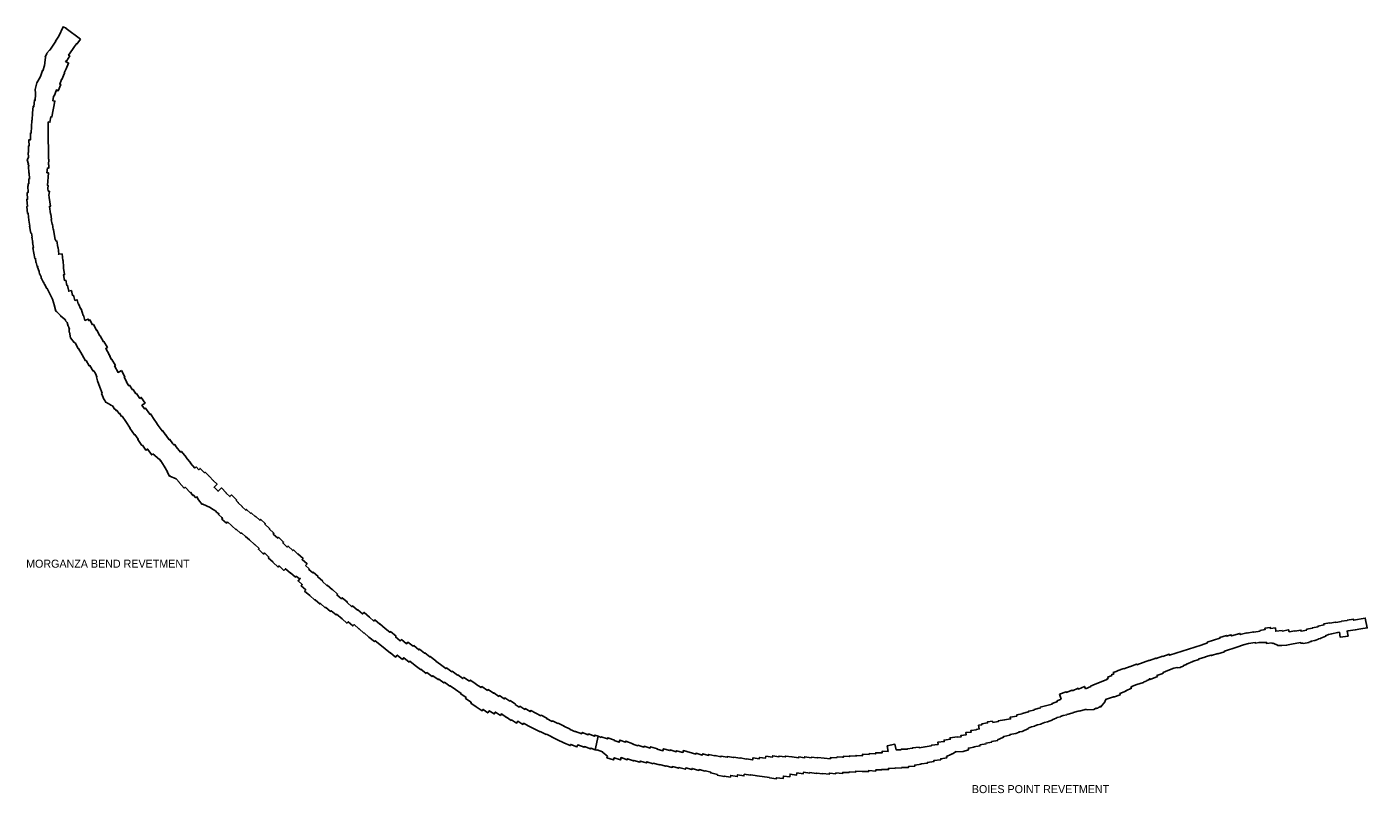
# Model space of a CAD drawing. Extents: x 2650582 to 3923188, y 277893 to 989177.
# Drawn here: x 3197064 to 3223870, y 809785 to 825119 of the extents above; entities that cross this region are included whole.
import ezdxf

# ---------------------------------------------------------------- set-up
doc = ezdxf.new("R2010")
doc.units = 0
doc.layers.add('Level 3', color=7, linetype='Continuous')

msp = doc.modelspace()

# ---------------------------------------------------------------- linework, layer by layer
at = {"layer": 'Level 3'}
for points in [[(3198137, 824875), (3197849, 825082), (3197852, 825090), (3197790, 825119), (3197703, 824935), (3197708, 824932), (3197640, 824831), (3197644, 824829), (3197593, 824751), (3197589, 824754), (3197522, 824651), (3197521, 824652), (3197463, 824590), (3197467, 824586), (3197462, 824588), (3197434, 824513), (3197436, 824513), (3197423, 824395), (3197424, 824395), (3197422, 824389), (3197423, 824389), (3197421, 824348), (3197382, 824240), (3197375, 824242), (3197341, 824128), (3197337, 824129), (3197334, 824111), (3197267, 823995), (3197262, 823996), (3197232, 823865), (3197234, 823865), (3197235, 823790), (3197240, 823767)], [(3197585, 823641), (3197598, 823722), (3197599, 823722), (3197602, 823737), (3197610, 823734), (3197656, 823855), (3197694, 823840), (3197743, 823965), (3197722, 823974), (3197760, 824068), (3197767, 824065), (3197820, 824194), (3197814, 824196), (3197850, 824279), (3197852, 824279), (3197901, 824393), (3197841, 824425), (3197848, 824437), (3197855, 824433), (3197922, 824535), (3197901, 824549), (3197976, 824664), (3198019, 824725), (3198017, 824727), (3198055, 824781), (3198064, 824775), (3198137, 824875)], [(3197240, 823767), (3197232, 823651), (3197215, 823652), (3197205, 823524), (3197189, 823525), (3197180, 823395), (3197176, 823395), (3197169, 823254), (3197165, 823254), (3197159, 823117), (3197160, 823116), (3197154, 822995), (3197140, 822995), (3197139, 822860), (3197108, 822860), (3197110, 822732), (3197097, 822732), (3197098, 822602), (3197093, 822602), (3197095, 822505), (3197074, 822459), (3197079, 822457), (3197072, 822455), (3197095, 822374), (3197090, 822372), (3197102, 822335), (3197102, 822330), (3197101, 822330), (3197104, 822197), (3197111, 822197), (3197115, 822073), (3197102, 822072), (3197105, 821981), (3197093, 821981), (3197093, 821936), (3197084, 821935), (3197091, 821803), (3197072, 821802), (3197079, 821666), (3197064, 821665), (3197078, 821527), (3197067, 821526), (3197081, 821385), (3197093, 821386), (3197108, 821252), (3197126, 821130), (3197118, 821128), (3197145, 820990), (3197155, 820992), (3197173, 820910)], [(3197494, 822468), (3197495, 822468), (3197493, 823064), (3197493, 823216), (3197526, 823210), (3197547, 823320), (3197566, 823316), (3197628, 823633), (3197585, 823641)], [(3197693, 820569), (3197693, 820570), (3197705, 820571), (3197689, 820706), (3197682, 820705), (3197668, 820834), (3197646, 820832), (3197641, 820858), (3197632, 820857), (3197599, 821065), (3197594, 821064), (3197577, 821168), (3197571, 821167), (3197554, 821265), (3197561, 821266), (3197543, 821376), (3197536, 821375), (3197515, 821524), (3197538, 821528), (3197511, 821707), (3197513, 821716), (3197510, 821717), (3197506, 821741), (3197516, 821828), (3197493, 821831), (3197485, 821886), (3197491, 821944), (3197476, 821946), (3197476, 821946), (3197501, 822195), (3197468, 822198), (3197480, 822295), (3197505, 822294), (3197506, 822353), (3197501, 822355), (3197505, 822468), (3197494, 822468)], [(3197173, 820910), (3197167, 820908), (3197183, 820804), (3197177, 820803), (3197195, 820701), (3197186, 820700), (3197222, 820486), (3197237, 820487), (3197247, 820404), (3197249, 820404), (3197270, 820325), (3197281, 820328), (3197284, 820313), (3197277, 820310), (3197309, 820222), (3197311, 820223), (3197320, 820171), (3197325, 820172), (3197349, 820115), (3197354, 820085), (3197361, 820086), (3197398, 820001), (3197407, 820005), (3197413, 819971), (3197421, 819972), (3197468, 819880), (3197470, 819881), (3197576, 819670), (3197580, 819673), (3197620, 819533), (3197615, 819532), (3197645, 819429), (3197655, 819432), (3197660, 819417), (3197666, 819419), (3197741, 819340), (3197744, 819331), (3197746, 819331), (3197835, 819253), (3197841, 819235), (3197870, 819201), (3197892, 819129), (3197896, 819131), (3197906, 819104), (3197919, 819071), (3197914, 819071), (3197914, 819009), (3197919, 819009), (3197937, 818898), (3197940, 818898), (3198013, 818804), (3198015, 818805), (3198017, 818800), (3198023, 818802), (3198035, 818792)], [(3198381, 819157), (3198327, 819254), (3198302, 819240), (3198290, 819271), (3198226, 819246), (3198196, 819347), (3198194, 819346), (3198152, 819473), (3198145, 819470), (3198097, 819579), (3198094, 819578), (3198069, 819658), (3198025, 819644), (3197996, 819748), (3197978, 819744), (3197955, 819841), (3197904, 819829), (3197880, 819945), (3197868, 819943), (3197847, 820049), (3197818, 820044), (3197798, 820156), (3197821, 820160), (3197801, 820287), (3197801, 820287), (3197798, 820309), (3197801, 820309), (3197791, 820445), (3197783, 820444), (3197770, 820576), (3197693, 820569)], [(3198959, 818242), (3198891, 818205), (3198819, 818333), (3198838, 818345), (3198766, 818465), (3198760, 818461), (3198724, 818522), (3198732, 818528), (3198708, 818562), (3198712, 818564), (3198644, 818684), (3198678, 818705), (3198606, 818822), (3198600, 818819), (3198531, 818938), (3198526, 818935), (3198466, 819051), (3198457, 819047), (3198398, 819166), (3198381, 819157)], [(3198035, 818792), (3198094, 818679), (3198099, 818682), (3198172, 818556), (3198169, 818554), (3198240, 818439), (3198250, 818445), (3198313, 818333), (3198327, 818340), (3198392, 818231), (3198404, 818238), (3198437, 818184), (3198453, 818146), (3198454, 818147), (3198466, 818118), (3198459, 818117), (3198479, 818039), (3198476, 818038), (3198527, 817908), (3198522, 817906), (3198571, 817787), (3198559, 817782), (3198614, 817653), (3198620, 817655), (3198643, 817604), (3198648, 817606), (3198738, 817557), (3198739, 817556), (3198740, 817556), (3198742, 817555), (3198745, 817550), (3198748, 817552), (3198775, 817537)], [(3200053, 816715), (3200022, 816765), (3200003, 816753), (3199983, 816778), (3199926, 816863), (3199914, 816855), (3199853, 816943), (3199852, 816942), (3199840, 816960), (3199837, 816958), (3199780, 817039), (3199770, 817032), (3199694, 817140), (3199693, 817139), (3199642, 817213), (3199625, 817242), (3199628, 817244), (3199535, 817376), (3199522, 817367), (3199437, 817492), (3199415, 817476), (3199367, 817547), (3199431, 817591), (3199354, 817704), (3199325, 817684), (3199257, 817783), (3199248, 817776), (3199189, 817865), (3199177, 817857), (3199119, 817949), (3199102, 817938), (3199059, 818008), (3199068, 818012), (3199012, 818111), (3199025, 818119), (3198959, 818242)], [(3198775, 817537), (3198825, 817463), (3198833, 817468), (3198856, 817436), (3198868, 817444), (3198911, 817381), (3198918, 817386), (3198960, 817325), (3198969, 817331), (3199043, 817224), (3199042, 817223), (3199131, 817092), (3199125, 817088), (3199217, 816956), (3199225, 816961), (3199292, 816866), (3199284, 816860), (3199367, 816743), (3199375, 816748), (3199446, 816648), (3199479, 816671), (3199562, 816554), (3199588, 816572)], [(3199588, 816572), (3199715, 816463), (3199720, 816468), (3199743, 816431), (3199747, 816434), (3199814, 816328), (3199813, 816327), (3199880, 816217), (3199873, 816213), (3199918, 816131), (3199929, 816138), (3199926, 816130), (3200051, 816074), (3200115, 816001), (3200112, 815999), (3200214, 815889), (3200232, 815906), (3200335, 815795), (3200347, 815805), (3200355, 815796), (3200348, 815791), (3200385, 815740), (3200398, 815749), (3200446, 815698), (3200466, 815716), (3200496, 815656), (3200572, 815562), (3200585, 815572), (3200583, 815568), (3200730, 815503), (3200730, 815503), (3200779, 815465), (3200779, 815466), (3200839, 815433), (3200863, 815403), (3200908, 815374), (3200897, 815362), (3200964, 815301), (3200979, 815284), (3200964, 815268), (3201056, 815185), (3201080, 815212)], [(3201248, 815643), (3201259, 815654), (3201160, 815753), (3201126, 815719), (3201049, 815790), (3201054, 815794), (3200955, 815893), (3200889, 815828), (3200811, 815906), (3200871, 815965), (3200794, 816042), (3200794, 816042), (3200717, 816119), (3200717, 816120), (3200629, 816207), (3200619, 816197), (3200530, 816285), (3200504, 816258), (3200452, 816314), (3200427, 816290), (3200341, 816388), (3200345, 816391), (3200249, 816502), (3200253, 816506), (3200155, 816624), (3200139, 816611), (3200054, 816715), (3200053, 816715)], [(3202637, 814338), (3202670, 814375), (3202571, 814460), (3202591, 814482), (3202485, 814574), (3202482, 814571), (3202395, 814652), (3202384, 814641), (3202289, 814730), (3202272, 814711), (3202184, 814793), (3202201, 814811), (3202098, 814907), (3202082, 814889), (3201994, 814971), (3202007, 814985), (3201912, 815074), (3201920, 815082), (3201825, 815170), (3201833, 815179), (3201742, 815264), (3201725, 815245), (3201642, 815323), (3201635, 815316), (3201552, 815394), (3201543, 815384), (3201460, 815462), (3201446, 815447), (3201370, 815518), (3201372, 815521), (3201289, 815598), (3201292, 815602), (3201248, 815643)], [(3201080, 815212), (3201166, 815132), (3201167, 815134), (3201251, 815056), (3201258, 815064), (3201341, 814986), (3201346, 814992), (3201357, 814982), (3201364, 814989), (3201437, 814922), (3201439, 814924), (3201515, 814853), (3201515, 814853), (3201618, 814758), (3201623, 814763), (3201711, 814682), (3201697, 814667), (3201799, 814571), (3201819, 814592), (3201906, 814510), (3201893, 814496), (3201988, 814407), (3201987, 814406), (3202089, 814310), (3202110, 814333), (3202205, 814244), (3202235, 814276), (3202335, 814189), (3202338, 814191), (3202436, 814106), (3202454, 814127)], [(3202454, 814127), (3202521, 814071), (3202531, 814083), (3202533, 814082), (3202490, 814031), (3202574, 813958), (3202554, 813934), (3202643, 813856), (3202621, 813830), (3202726, 813740), (3202724, 813738), (3202822, 813649), (3202828, 813655), (3202928, 813569), (3202939, 813582), (3203033, 813497), (3203041, 813506), (3203139, 813421), (3203152, 813435), (3203248, 813352), (3203259, 813365), (3203368, 813271), (3203370, 813273), (3203467, 813186), (3203493, 813215), (3203587, 813132), (3203611, 813160), (3203706, 813075), (3203708, 813077), (3203806, 812990), (3203808, 812992), (3203904, 812908), (3203906, 812910), (3204016, 812819), (3204031, 812836), (3204124, 812760), (3204127, 812763), (3204232, 812674), (3204233, 812674), (3204335, 812587), (3204339, 812591), (3204439, 812508), (3204472, 812548), (3204575, 812462), (3204604, 812496), (3204710, 812407), (3204724, 812424), (3204828, 812337), (3204832, 812342), (3204936, 812258), (3204941, 812264), (3205050, 812180)], [(3205241, 812428), (3205246, 812435), (3205133, 812522), (3205125, 812513), (3205026, 812593), (3205019, 812585), (3204919, 812668), (3204906, 812653), (3204803, 812740), (3204789, 812724), (3204687, 812810), (3204658, 812775), (3204557, 812859), (3204534, 812831), (3204438, 812912), (3204449, 812925), (3204338, 813020), (3204325, 813005), (3204232, 813081), (3204124, 813171), (3204121, 813168), (3204023, 813253), (3204003, 813230), (3203915, 813307), (3203809, 813403), (3203781, 813371), (3203686, 813455), (3203680, 813449), (3203581, 813536), (3203564, 813517), (3203471, 813599), (3203477, 813605), (3203372, 813697), (3203355, 813677), (3203266, 813754), (3203279, 813768), (3203179, 813858), (3203176, 813855), (3203072, 813946), (3203067, 813940), (3202978, 814020), (3202983, 814025), (3202883, 814111), (3202890, 814119), (3202791, 814206), (3202782, 814195), (3202702, 814264), (3202710, 814273), (3202637, 814338)], [(3222660, 813046), (3222657, 813065), (3222773, 813086), (3222771, 813093), (3222888, 813116), (3222886, 813130), (3223004, 813152), (3223001, 813171), (3223120, 813192), (3223122, 813188), (3223239, 813209), (3223241, 813203), (3223354, 813222), (3223353, 813226), (3223472, 813241), (3223472, 813244), (3223596, 813265), (3223599, 813245), (3223832, 813288), (3223870, 813093), (3223745, 813074), (3223745, 813076), (3223632, 813057), (3223632, 813051), (3223490, 813032), (3223469, 813029), (3223486, 812929), (3223331, 812904), (3223315, 813007), (3223276, 813001), (3223276, 812998), (3223161, 812977), (3223161, 812974), (3223094, 812962), (3223039, 812937), (3223042, 812927), (3222945, 812886), (3222940, 812893), (3222940, 812879), (3222894, 812873), (3222894, 812867), (3222823, 812840), (3222823, 812838), (3222749, 812827), (3222750, 812820), (3222706, 812806), (3222707, 812803), (3222588, 812778)], [(3219779, 812528), (3219783, 812518), (3219910, 812565), (3219917, 812546), (3220299, 812669), (3220299, 812668), (3220421, 812708), (3220422, 812704), (3220548, 812750), (3220674, 812791), (3220670, 812804), (3220924, 812886), (3220921, 812900), (3221053, 812943), (3221060, 812927), (3221146, 812955), (3221155, 812931), (3221323, 812982), (3221331, 812960), (3221465, 812995), (3221466, 812989), (3221600, 813012), (3221601, 813007), (3221728, 813029), (3221726, 813040), (3221829, 813059), (3221826, 813090)], [(3221826, 813090), (3221932, 813101), (3221934, 813081), (3222033, 813091), (3222040, 813027), (3222169, 813038), (3222170, 813024)], [(3222170, 813024), (3222299, 813054), (3222309, 813013)], [(3222309, 813013), (3222423, 813034), (3222425, 813030), (3222543, 813050), (3222549, 813026), (3222660, 813046)], [(3221968, 812791), (3221859, 812780), (3221857, 812801), (3221799, 812799), (3221798, 812803), (3221768, 812797), (3221767, 812800), (3221709, 812801), (3221709, 812803), (3221633, 812789), (3221630, 812800), (3221497, 812778), (3221396, 812754), (3221263, 812707), (3221263, 812709), (3221013, 812627), (3221016, 812616), (3220884, 812572), (3220881, 812580), (3220754, 812538), (3220751, 812550), (3220630, 812511), (3220631, 812508), (3220501, 812471), (3220504, 812461), (3220378, 812423), (3220380, 812417), (3220255, 812370), (3220258, 812360), (3220193, 812337), (3220196, 812330), (3220134, 812307), (3220134, 812302), (3220068, 812295), (3220068, 812303), (3220005, 812285), (3219884, 812243), (3219885, 812238)], [(3222588, 812778), (3222585, 812784), (3222538, 812788), (3222539, 812797), (3222353, 812765), (3222353, 812764), (3222257, 812747), (3222258, 812745), (3222162, 812737), (3222161, 812740), (3222080, 812738), (3222079, 812746), (3222004, 812781), (3222006, 812785), (3221969, 812781), (3221968, 812791)], [(3218692, 812083), (3218682, 812107), (3218763, 812139), (3218757, 812155), (3218802, 812173), (3218793, 812197), (3218872, 812228), (3218871, 812231), (3219003, 812280), (3219005, 812274), (3219132, 812322), (3219133, 812319), (3219258, 812367), (3219263, 812356), (3219388, 812403), (3219391, 812397), (3219517, 812445), (3219519, 812439), (3219645, 812487), (3219649, 812479), (3219779, 812528)], [(3208430, 810656), (3208493, 810923), (3208426, 810948), (3208418, 810926), (3208298, 810971), (3208292, 810955), (3208172, 811001), (3208161, 810973), (3208040, 811021), (3208038, 811015), (3207928, 811062), (3207929, 811065), (3207807, 811123), (3207809, 811129), (3207688, 811186), (3207685, 811180), (3207577, 811232), (3207572, 811223), (3207458, 811277), (3207463, 811287), (3207348, 811345), (3207343, 811336), (3207245, 811388), (3207243, 811385), (3207146, 811443), (3207131, 811418), (3207033, 811477), (3207024, 811462), (3206925, 811525), (3206913, 811507), (3206833, 811563), (3206835, 811566), (3206732, 811637), (3206727, 811629), (3206627, 811695), (3206612, 811673), (3206515, 811738), (3206504, 811722), (3206403, 811794), (3206396, 811785), (3206289, 811859), (3206276, 811841), (3206164, 811918), (3206150, 811898), (3206043, 811969), (3206045, 811973), (3205932, 812050), (3205916, 812027), (3205804, 812103), (3205787, 812078), (3205682, 812153), (3205677, 812147), (3205571, 812225), (3205563, 812214), (3205456, 812293), (3205447, 812280), (3205338, 812360), (3205336, 812357), (3205241, 812428)], [(3219885, 812238), (3219787, 812199), (3219791, 812187), (3219762, 812176), (3219666, 812140), (3219674, 812122), (3219528, 812061), (3219521, 812078), (3219514, 812075), (3219518, 812062), (3219460, 812040), (3219461, 812034), (3219395, 812005), (3219396, 812001), (3219264, 811958), (3219263, 811961), (3219143, 811914)], [(3205050, 812180), (3205064, 812198), (3205169, 812118), (3205183, 812136), (3205291, 812057), (3205301, 812070), (3205407, 811992), (3205417, 812005), (3205524, 811927), (3205531, 811936), (3205638, 811860), (3205636, 811858), (3205749, 811782), (3205741, 811770), (3205848, 811697), (3205838, 811682), (3205953, 811604), (3205942, 811588), (3206052, 811513), (3206051, 811511), (3206168, 811431), (3206188, 811460), (3206284, 811393), (3206314, 811435), (3206411, 811370), (3206437, 811409), (3206537, 811343), (3206556, 811372), (3206656, 811303), (3206658, 811306), (3206751, 811242), (3206758, 811252), (3206858, 811189), (3206881, 811225), (3206986, 811162), (3207000, 811186), (3207101, 811125), (3207103, 811127), (3207211, 811070), (3207212, 811073), (3207328, 811015), (3207329, 811018), (3207454, 810960), (3207456, 810965), (3207561, 810915), (3207560, 810912), (3207678, 810856), (3207675, 810850), (3207801, 810791), (3207802, 810794), (3207931, 810738), (3207941, 810762), (3208065, 810712), (3208082, 810752), (3208210, 810703), (3208215, 810717), (3208339, 810671), (3208345, 810689), (3208430, 810656)], [(3218236, 811872), (3218342, 811919), (3218339, 811926), (3218429, 811965), (3218427, 811968), (3218552, 812015), (3218553, 812012), (3218666, 812058), (3218660, 812070), (3218692, 812083)], [(3216973, 811372), (3216971, 811381), (3217097, 811411), (3217094, 811424), (3217209, 811449), (3217207, 811458), (3217334, 811491), (3217330, 811508), (3217572, 811568), (3217567, 811582), (3217674, 811617), (3217668, 811633), (3217753, 811666)], [(3217715, 811766), (3217847, 811816), (3217852, 811803), (3217973, 811847), (3217979, 811835), (3218087, 811884), (3218096, 811867), (3218215, 811921), (3218236, 811872)], [(3217753, 811666), (3217715, 811766)], [(3218921, 811778), (3218930, 811754), (3218799, 811708), (3218797, 811714), (3218676, 811670), (3218674, 811674), (3218637, 811660), (3218643, 811656), (3218621, 811629)], [(3219143, 811914), (3219155, 811885), (3219041, 811836), (3219045, 811829), (3218921, 811778)], [(3218230, 811462), (3218117, 811427), (3218115, 811433), (3217992, 811399), (3217992, 811396), (3217864, 811359), (3217864, 811355), (3217787, 811342), (3217789, 811338), (3217735, 811319), (3217736, 811314), (3217660, 811298), (3217662, 811291), (3217600, 811265), (3217578, 811262), (3217581, 811255), (3217479, 811214), (3217479, 811211), (3217419, 811201), (3217349, 811174), (3217349, 811168), (3217278, 811153), (3217278, 811150), (3217221, 811132), (3217221, 811126), (3217155, 811116), (3217155, 811114), (3217092, 811088)], [(3218621, 811629), (3218628, 811623), (3218545, 811511), (3218529, 811522), (3218532, 811516), (3218495, 811500), (3218482, 811489), (3218466, 811487), (3218449, 811479), (3218447, 811484), (3218437, 811483), (3218403, 811462), (3218283, 811454), (3218254, 811459), (3218249, 811457), (3218249, 811459), (3218230, 811462)], [(3215669, 810903), (3215748, 810911), (3215745, 810941), (3215848, 810952), (3215842, 810998), (3215950, 811009), (3215946, 811041), (3216054, 811055), (3216054, 811062), (3216110, 811071), (3216097, 811145), (3216165, 811156), (3216162, 811170), (3216279, 811190), (3216275, 811211), (3216376, 811226), (3216380, 811202)], [(3216380, 811202), (3216493, 811217), (3216492, 811230), (3216617, 811250), (3216617, 811252), (3216739, 811270), (3216733, 811309), (3216860, 811329), (3216860, 811351), (3216973, 811372)], [(3208678, 810528), (3208677, 810527), (3208578, 810608), (3208580, 810615), (3208468, 810655), (3208464, 810644), (3208430, 810656), (3208493, 810923), (3208548, 810902), (3208553, 810915), (3208675, 810871), (3208684, 810896), (3208815, 810847), (3208812, 810840)], [(3214268, 810736), (3214425, 810766), (3214447, 810655), (3214550, 810656), (3214549, 810665), (3214679, 810667), (3214679, 810672), (3214778, 810683), (3214777, 810693), (3214907, 810709), (3214910, 810695), (3215027, 810710), (3215026, 810716), (3215155, 810733), (3215154, 810743), (3215287, 810760), (3215282, 810803), (3215411, 810819), (3215407, 810848), (3215531, 810864), (3215528, 810893), (3215668, 810911), (3215669, 810903)], [(3216725, 810955), (3216726, 810944), (3216600, 810921), (3216602, 810908), (3216578, 810905), (3216582, 810897), (3216479, 810851), (3216481, 810842), (3216359, 810820), (3216361, 810809), (3216244, 810789), (3216247, 810772), (3216126, 810752), (3216129, 810730), (3216006, 810713), (3216007, 810705), (3215895, 810689), (3215899, 810656), (3215787, 810621), (3215649, 810611), (3215648, 810622)], [(3217092, 811088), (3217095, 811080), (3216967, 811022), (3216908, 811013), (3216911, 811005), (3216842, 810981), (3216842, 810978), (3216724, 810958), (3216725, 810955)], [(3208812, 810840), (3208908, 810806), (3208924, 810848), (3209039, 810808), (3209047, 810827), (3209187, 810776), (3209184, 810767), (3209281, 810733), (3209285, 810745), (3209407, 810708), (3209412, 810723), (3209531, 810688), (3209539, 810713), (3209674, 810671), (3209672, 810666), (3209785, 810634), (3209797, 810673), (3209925, 810638), (3209929, 810652), (3210052, 810616), (3210058, 810635), (3210185, 810600), (3210197, 810639), (3210443, 810569), (3210448, 810583), (3210573, 810547), (3210581, 810574), (3210698, 810542), (3210703, 810562), (3210826, 810531), (3210830, 810542), (3210947, 810515), (3210950, 810528), (3211072, 810504), (3211075, 810518), (3211198, 810497), (3211200, 810506), (3211329, 810483), (3211331, 810492), (3211459, 810467), (3211460, 810473)], [(3211460, 810473), (3211580, 810452), (3211587, 810493), (3211711, 810473), (3211715, 810502), (3211839, 810489), (3211844, 810524), (3211977, 810507), (3211982, 810533), (3212106, 810514), (3212109, 810529), (3212233, 810511), (3212236, 810529), (3212366, 810510), (3212367, 810514), (3212498, 810494), (3212505, 810510), (3212619, 810496), (3212622, 810513), (3212752, 810496), (3212753, 810505), (3212880, 810490), (3212881, 810498), (3213008, 810483), (3213009, 810487), (3213134, 810475), (3213136, 810497), (3213166, 810494), (3213267, 810502), (3213268, 810512), (3213375, 810503), (3213394, 810505), (3213395, 810524), (3213519, 810517), (3213520, 810535), (3213648, 810526), (3213649, 810540), (3213778, 810533), (3213780, 810567), (3213910, 810560), (3213911, 810578), (3214037, 810572), (3214041, 810594), (3214167, 810590), (3214167, 810624), (3214290, 810621), (3214268, 810736)], [(3215648, 810622), (3215574, 810576), (3215574, 810572), (3215567, 810571), (3215545, 810558), (3215542, 810562), (3215459, 810519), (3215463, 810490), (3215340, 810474), (3215341, 810453), (3215203, 810437), (3215206, 810417), (3215075, 810400), (3215077, 810388), (3214948, 810374), (3214950, 810363), (3214823, 810346), (3214824, 810327), (3214696, 810317), (3214695, 810299), (3214560, 810297), (3214559, 810286)], [(3211540, 810143), (3211412, 810165), (3211406, 810132), (3211278, 810154), (3211271, 810116), (3211142, 810140), (3211136, 810107), (3211011, 810129), (3211009, 810117), (3210873, 810146), (3210876, 810159), (3210743, 810191), (3210745, 810203), (3210634, 810233), (3210632, 810226), (3210511, 810258), (3210505, 810241), (3210369, 810281), (3210363, 810259), (3210242, 810292), (3210234, 810264), (3210107, 810300), (3210102, 810285), (3209977, 810319), (3209972, 810300), (3209845, 810335), (3209842, 810324), (3209718, 810359), (3209715, 810350), (3209592, 810386), (3209589, 810376), (3209465, 810413), (3209458, 810392), (3209333, 810429), (3209326, 810405), (3209203, 810442), (3209200, 810432), (3209078, 810474), (3209072, 810454), (3208948, 810498), (3208934, 810451), (3208811, 810494), (3208796, 810450), (3208666, 810496), (3208678, 810528)], [(3214559, 810286), (3214430, 810291), (3214429, 810281), (3214299, 810283), (3214297, 810259), (3214162, 810261), (3214161, 810252), (3214045, 810255), (3214042, 810229), (3213902, 810236), (3213900, 810216), (3213771, 810222), (3213770, 810216), (3213641, 810223), (3213640, 810208), (3213512, 810215), (3213510, 810196), (3213382, 810201), (3213379, 810181), (3213246, 810192), (3213243, 810174), (3213114, 810188), (3213112, 810168), (3212985, 810181), (3212984, 810173), (3212854, 810189), (3212853, 810180), (3212723, 810197), (3212721, 810187), (3212595, 810204), (3212592, 810175), (3212464, 810191), (3212458, 810148), (3212329, 810167), (3212321, 810111), (3212194, 810129), (3212187, 810076), (3212056, 810095), (3212053, 810074), (3211914, 810094), (3211915, 810097), (3211669, 810134), (3211669, 810131), (3211541, 810153), (3211540, 810143)]]:
    msp.add_lwpolyline(points, dxfattribs=at)

# ---------------------------------------------------------------- texts
for s, p in [('MORGANZA BEND REVETMENT', (3197051, 814297)), ('BOIES POINT REVETMENT', (3215963, 809787))]:
    msp.add_text(s, height=160, dxfattribs=at).set_placement(p)

doc.saveas('drawing.dxf')
